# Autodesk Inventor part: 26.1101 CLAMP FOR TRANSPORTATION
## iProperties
Created: 2012-10
Part Number: 26.1101 CLAMP FOR TRANSPORTATION
Document SubType Name: Modeling
Designer: Administrator
Density: 7.85 g/cm^3
Material: Steel
Mass: 657.233 g
Surface Area: 328.609 cm^2
Volume: 83.724 cm^3
Author: Administrator
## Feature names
1. Base1
